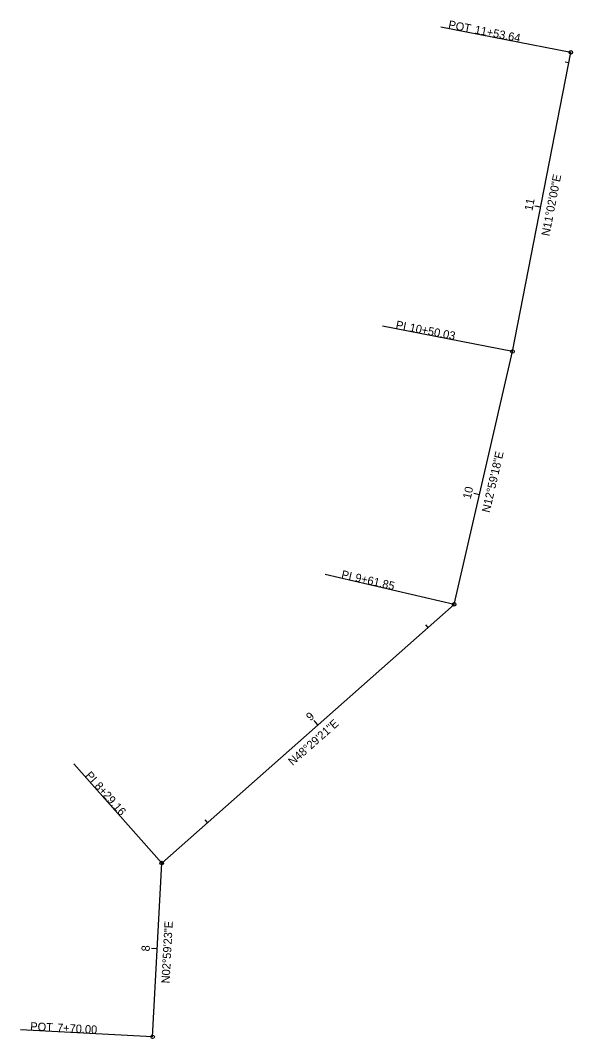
# Model space of a CAD drawing. Extents: x 2319255 to 2319442, y 733509 to 733856.
import ezdxf

# ---------------------------------------------------------------- set-up
doc = ezdxf.new("R2010")
doc.units = 0
for name, color, linetype in [('GE_P_Alignment', 7, 'Continuous'), ('GE_P_Alignment_1000_Bearings', 7, 'Continuous'), ('GE_P_Alignment_1000_Cardinal_Points', 7, 'Continuous'), ('GE_P_Alignment_1000_Stations', 7, 'Continuous'), ('GE_P_Alignment_100_Bearings', 7, 'Continuous'), ('GE_P_Alignment_100_Cardinal_Points', 7, 'Continuous'), ('GE_P_Alignment_100_Stations', 7, 'Continuous'), ('GE_P_Alignment_500_Bearings', 7, 'Continuous'), ('GE_P_Alignment_500_Cardinal_Points', 7, 'Continuous'), ('GE_P_Alignment_500_Stations', 7, 'Continuous')]:
    doc.layers.add(name, color=color, linetype=linetype)

msp = doc.modelspace()

# ---------------------------------------------------------------- linework, layer by layer
at = {"layer": 'GE_P_Alignment'}
for p, q in [((2319421.97, 733743.03), (2319441.8, 733844.72)), ((2319402.15, 733657.1), (2319421.97, 733743.03)), ((2319302.79, 733569.16), (2319402.15, 733657.1)), ((2319299.7, 733510.08), (2319302.79, 733569.16))]:
    msp.add_line(p, q, dxfattribs=at)
at = {"layer": 'GE_P_Alignment_1000_Cardinal_Points'}
for p, q in [((2319441.8, 733844.72), (2319397.63, 733853.33)), ((2319421.97, 733743.03), (2319377.8, 733751.64)), ((2319402.15, 733657.1), (2319358.3, 733667.21)), ((2319302.79, 733569.16), (2319272.97, 733602.86)), ((2319299.7, 733510.08), (2319254.77, 733512.43))]:
    msp.add_line(p, q, dxfattribs=at)
for centre in [(2319441.8, 733844.72), (2319421.97, 733743.03), (2319402.15, 733657.1), (2319302.79, 733569.16), (2319299.7, 733510.08)]:
    msp.add_circle(centre, 0.6, dxfattribs=at)
at = {"layer": 'GE_P_Alignment_1000_Stations'}
msp.add_line((2319410.72, 733694.28), (2319408.78, 733694.73), dxfattribs=at)
at = {"layer": 'GE_P_Alignment_100_Cardinal_Points'}
for p, q in [((2319441.8, 733844.72), (2319397.63, 733853.33)), ((2319421.97, 733743.03), (2319377.8, 733751.64)), ((2319402.15, 733657.1), (2319358.3, 733667.21)), ((2319302.79, 733569.16), (2319272.97, 733602.86)), ((2319299.7, 733510.08), (2319254.77, 733512.43))]:
    msp.add_line(p, q, dxfattribs=at)
for centre in [(2319441.8, 733844.72), (2319421.97, 733743.03), (2319402.15, 733657.1), (2319302.79, 733569.16), (2319299.7, 733510.08)]:
    msp.add_circle(centre, 0.6, dxfattribs=at)
at = {"layer": 'GE_P_Alignment_100_Stations'}
for p, q in [((2319441.1, 733841.15), (2319439.92, 733841.38)), ((2319431.53, 733792.07), (2319429.57, 733792.45)), ((2319421.96, 733743), (2319420.79, 733743.27)), ((2319410.72, 733694.28), (2319408.78, 733694.73)), ((2319393.28, 733649.25), (2319392.48, 733650.15)), ((2319355.84, 733616.11), (2319354.51, 733617.61)), ((2319318.39, 733582.97), (2319317.6, 733583.87)), ((2319301.27, 733540.04), (2319299.27, 733540.14))]:
    msp.add_line(p, q, dxfattribs=at)
at = {"layer": 'GE_P_Alignment_500_Cardinal_Points'}
for p, q in [((2319441.8, 733844.72), (2319397.63, 733853.33)), ((2319421.97, 733743.03), (2319377.8, 733751.64)), ((2319402.15, 733657.1), (2319358.3, 733667.21)), ((2319302.79, 733569.16), (2319272.97, 733602.86)), ((2319299.7, 733510.08), (2319254.77, 733512.43))]:
    msp.add_line(p, q, dxfattribs=at)
for centre in [(2319441.8, 733844.72), (2319421.97, 733743.03), (2319402.15, 733657.1), (2319302.79, 733569.16), (2319299.7, 733510.08)]:
    msp.add_circle(centre, 0.6, dxfattribs=at)
at = {"layer": 'GE_P_Alignment_500_Stations'}
for p, q in [((2319431.53, 733792.07), (2319430.35, 733792.3)), ((2319410.72, 733694.28), (2319408.78, 733694.73)), ((2319355.84, 733616.11), (2319355.04, 733617.01)), ((2319301.27, 733540.04), (2319300.07, 733540.1))]:
    msp.add_line(p, q, dxfattribs=at)

# ---------------------------------------------------------------- texts
at = {"layer": 'GE_P_Alignment_1000_Bearings'}
for s, rotation, p in [('N11°02\'00"E', 78.9666, (2319434.48, 733782.12)), ('N12°59\'18"E', 77.0117, (2319414.22, 733688.09)), ('N48°29\'21"E', 41.5109, (2319347.28, 733602.13)), ('N02°59\'23"E', 87.0102, (2319305.46, 733528.2))]:
    msp.add_text(s, height=2.8, rotation=rotation, dxfattribs=at).set_placement(p)
at = {"layer": 'GE_P_Alignment_1000_Cardinal_Points'}
for s, rotation, p in [('POT', 348.9666, (2319399.99, 733852.92)), ('11+53.64', 348.9666, (2319408.95, 733851.17)), ('PI', 348.9666, (2319382.13, 733750.85)), ('10+50.03', 348.9666, (2319386.82, 733749.93)), ('PI', 347.0117, (2319363.63, 733666.03)), ('9+61.85', 347.0117, (2319368.29, 733664.96)), ('PI', 311.5109, (2319276.62, 733598.8)), ('8+29.16', 311.5109, (2319279.79, 733595.22)), ('POT', 357.0102, (2319258.06, 733512.3)), ('7+70.00', 357.0102, (2319267.18, 733511.83))]:
    msp.add_text(s, height=2.8, rotation=rotation, dxfattribs=at).set_placement(p)
at = {"layer": 'GE_P_Alignment_1000_Stations'}
msp.add_text('10', height=2.8, rotation=77.0117, dxfattribs=at).set_placement((2319407.75, 733692.71))
at = {"layer": 'GE_P_Alignment_100_Bearings'}
for s, rotation, p in [('N11°02\'00"E', 78.9666, (2319434.48, 733782.12)), ('N12°59\'18"E', 77.0117, (2319414.22, 733688.09)), ('N48°29\'21"E', 41.5109, (2319347.28, 733602.13)), ('N02°59\'23"E', 87.0102, (2319305.46, 733528.2))]:
    msp.add_text(s, height=2.8, rotation=rotation, dxfattribs=at).set_placement(p)
at = {"layer": 'GE_P_Alignment_100_Cardinal_Points'}
for s, rotation, p in [('POT', 348.9666, (2319399.99, 733852.92)), ('11+53.64', 348.9666, (2319408.95, 733851.17)), ('PI', 348.9666, (2319382.13, 733750.85)), ('10+50.03', 348.9666, (2319386.82, 733749.93)), ('PI', 347.0117, (2319363.63, 733666.03)), ('9+61.85', 347.0117, (2319368.29, 733664.96)), ('PI', 311.5109, (2319276.62, 733598.8)), ('8+29.16', 311.5109, (2319279.79, 733595.22)), ('POT', 357.0102, (2319258.06, 733512.3)), ('7+70.00', 357.0102, (2319267.18, 733511.83))]:
    msp.add_text(s, height=2.8, rotation=rotation, dxfattribs=at).set_placement(p)
at = {"layer": 'GE_P_Alignment_100_Stations'}
for s, rotation, p in [('11', 78.9666, (2319428.72, 733790.71)), ('10', 77.0117, (2319407.75, 733692.71)), ('9', 41.5109, (2319353.34, 733617.3)), ('8', 87.0102, (2319298.67, 733539.07))]:
    msp.add_text(s, height=2.8, rotation=rotation, dxfattribs=at).set_placement(p)
at = {"layer": 'GE_P_Alignment_500_Bearings'}
for s, rotation, p in [('N11°02\'00"E', 78.9666, (2319434.48, 733782.12)), ('N12°59\'18"E', 77.0117, (2319414.22, 733688.09)), ('N48°29\'21"E', 41.5109, (2319347.28, 733602.13)), ('N02°59\'23"E', 87.0102, (2319305.46, 733528.2))]:
    msp.add_text(s, height=2.8, rotation=rotation, dxfattribs=at).set_placement(p)
at = {"layer": 'GE_P_Alignment_500_Cardinal_Points'}
for s, rotation, p in [('POT', 348.9666, (2319399.99, 733852.92)), ('11+53.64', 348.9666, (2319408.95, 733851.17)), ('PI', 348.9666, (2319382.13, 733750.85)), ('10+50.03', 348.9666, (2319386.82, 733749.93)), ('PI', 347.0117, (2319363.63, 733666.03)), ('9+61.85', 347.0117, (2319368.29, 733664.96)), ('PI', 311.5109, (2319276.62, 733598.8)), ('8+29.16', 311.5109, (2319279.79, 733595.22)), ('POT', 357.0102, (2319258.06, 733512.3)), ('7+70.00', 357.0102, (2319267.18, 733511.83))]:
    msp.add_text(s, height=2.8, rotation=rotation, dxfattribs=at).set_placement(p)
at = {"layer": 'GE_P_Alignment_500_Stations'}
msp.add_text('10', height=2.8, rotation=77.0117, dxfattribs=at).set_placement((2319407.75, 733692.71))

doc.saveas('drawing.dxf')
